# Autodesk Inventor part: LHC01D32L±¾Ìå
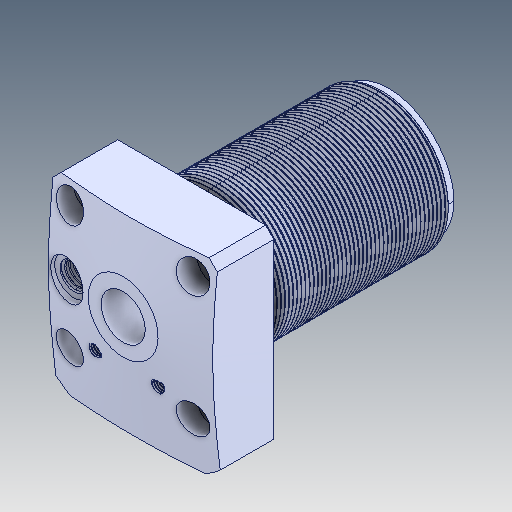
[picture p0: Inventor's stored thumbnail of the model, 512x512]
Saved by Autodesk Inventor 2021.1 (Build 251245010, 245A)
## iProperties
Created: 2021-06
Part Number: LHC01D32L±¾Ìå
Material: Ogólny
Document SubType Name: Modeling
Designer: user
Density: 1 g/cm^3
Appearance: Domyślna
Author: user
Revision Number: ÈÎºÎ
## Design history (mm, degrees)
feature "NONE"
node "Bryła1"
